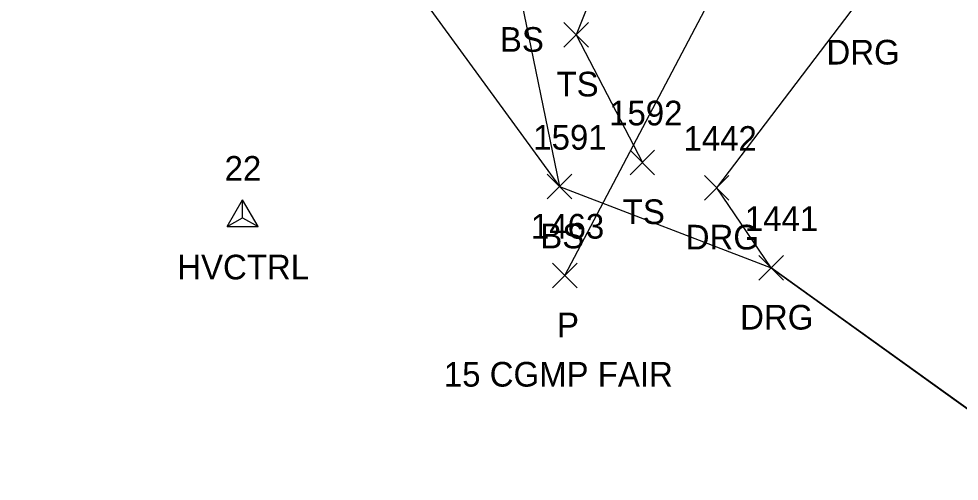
# Model space of a CAD drawing. Extents: x 1461855 to 1464118, y 556196 to 557441.
# Drawn here: x 1462341 to 1462417.3, y 556261.8 to 556299.3 of the extents above; entities that cross this region are included whole.
import ezdxf

# ---------------------------------------------------------------- set-up
doc = ezdxf.new("R2010")
doc.units = 0
for name, color, linetype in [('C_A', 7, 'Continuous'), ('C_I', 7, 'Continuous'), ('CPSM', 7, 'Continuous'), ('D_A', 7, 'Continuous'), ('D_C', 7, 'Continuous'), ('D_I', 7, 'Continuous'), ('D_TIC', 7, 'Continuous'), ('DCP', 7, 'Continuous'), ('L_A', 7, 'Continuous'), ('L_I', 7, 'Continuous'), ('L_TIC', 7, 'Continuous'), ('LELB', 7, 'Continuous'), ('LSOGP', 7, 'Continuous'), ('R_A', 7, 'Continuous'), ('R_I', 7, 'Continuous'), ('R_TIC', 7, 'Continuous'), ('RDG', 7, 'Continuous')]:
    doc.layers.add(name, color=color, linetype=linetype)

msp = doc.modelspace()

# ---------------------------------------------------------------- linework, layer by layer
at = {"layer": 'CPSM'}
for p, q in [((1462357.875, 556282.401), (1462359.125, 556284.567)), ((1462360.375, 556282.401), (1462359.125, 556284.567)), ((1462359.125, 556283.123), (1462359.125, 556284.567)), ((1462357.875, 556282.401), (1462359.125, 556283.123)), ((1462359.125, 556283.123), (1462359.125, 556283.123)), ((1462359.125, 556283.123), (1462360.375, 556282.401)), ((1462357.875, 556282.401), (1462360.375, 556282.401))]:
    msp.add_line(p, q, dxfattribs=at)
at = {"layer": 'D_TIC'}
for points in [[(1462384.254, 556277.429), (1462386.254, 556279.429)], [(1462386.254, 556277.429), (1462384.254, 556279.429)]]:
    msp.add_lwpolyline(points, dxfattribs=at)
at = {"layer": 'DCP'}
msp.add_lwpolyline([(1462385.254, 556278.429), (1462450.218, 556401.665)], dxfattribs=at)
at = {"layer": 'L_TIC'}
for points in [[(1462385.181, 556296.957), (1462387.181, 556298.957)], [(1462387.181, 556296.957), (1462385.181, 556298.957)], [(1462390.554, 556286.61), (1462392.554, 556288.61)], [(1462392.554, 556286.61), (1462390.554, 556288.61)], [(1462383.833, 556284.643), (1462385.833, 556286.643)], [(1462385.833, 556284.643), (1462383.833, 556286.643)]]:
    msp.add_lwpolyline(points, dxfattribs=at)
at = {"layer": 'LELB'}
for points in [[(1462383.947, 556337.636), (1462386.024, 556333.458), (1462395.339, 556327.216), (1462385.927, 556310.567), (1462381.555, 556301.576), (1462384.833, 556285.643)], [(1462395.339, 556327.216), (1462398.801, 556322.251), (1462390.071, 556307.672), (1462386.181, 556297.957), (1462391.554, 556287.61)]]:
    msp.add_lwpolyline(points, dxfattribs=at)
at = {"layer": 'LSOGP'}
msp.add_lwpolyline([(1462337.181, 556366.3), (1462343.781, 556341.464), (1462347.875, 556323.015), (1462349.416, 556312.261), (1462360.161, 556305.037), (1462370.947, 556304.696), (1462384.833, 556285.643), (1462401.999, 556279.054), (1462407.007, 556275.465), (1462412.015, 556271.876), (1462417.023, 556268.287), (1462422.031, 556264.698)], dxfattribs=at)
at = {"layer": 'R_TIC'}
for points in [[(1462396.585, 556284.549), (1462398.585, 556286.549)], [(1462398.585, 556284.549), (1462396.585, 556286.549)], [(1462400.999, 556278.054), (1462402.999, 556280.054)], [(1462402.999, 556278.054), (1462400.999, 556280.054)]]:
    msp.add_lwpolyline(points, dxfattribs=at)
at = {"layer": 'RDG'}
msp.add_lwpolyline([(1462471.701, 556261.761), (1462438.324, 556287.482), (1462422.031, 556264.698), (1462401.999, 556279.054), (1462397.585, 556285.549), (1462409.003, 556300.547), (1462420.819, 556315.873), (1462433.109, 556307.34), (1462433.646, 556308.394), (1462436.243, 556314.92), (1462427.467, 556321.191), (1462422.766, 556315.355)], dxfattribs=at)

# ---------------------------------------------------------------- texts
at = {"layer": 'C_A'}
msp.add_text('HVCTRL', height=2, dxfattribs=at).set_placement((1462353.818, 556278.123))
at = {"layer": 'C_I'}
msp.add_text('22', height=2, dxfattribs=at).set_placement((1462357.661, 556286.123))
at = {"layer": 'D_A'}
msp.add_text('P', height=2, dxfattribs=at).set_placement((1462384.632, 556273.429))
at = {"layer": 'D_C'}
msp.add_text('15 CGMP FAIR', height=2, dxfattribs=at).set_placement((1462375.451, 556269.429))
at = {"layer": 'D_I'}
msp.add_text('1463', height=2, dxfattribs=at).set_placement((1462382.514, 556281.429))
at = {"layer": 'L_A'}
for s, p in [('BS', (1462379.996, 556296.576)), ('TS', (1462384.59, 556292.957)), ('TS', (1462389.964, 556282.61)), ('BS', (1462383.274, 556280.643))]:
    msp.add_text(s, height=2, dxfattribs=at).set_placement(p)
at = {"layer": 'L_I'}
for s, p in [('1592', (1462388.862, 556290.61)), ('1591', (1462382.707, 556288.643))]:
    msp.add_text(s, height=2, dxfattribs=at).set_placement(p)
at = {"layer": 'R_A'}
for p in [(1462406.491, 556295.547), (1462395.073, 556280.549), (1462399.487, 556274.054)]:
    msp.add_text('DRG', height=2, dxfattribs=at).set_placement(p)
at = {"layer": 'R_I'}
for s, p in [('1442', (1462394.892, 556288.549)), ('1441', (1462399.873, 556282.054))]:
    msp.add_text(s, height=2, dxfattribs=at).set_placement(p)

doc.saveas('drawing.dxf')
